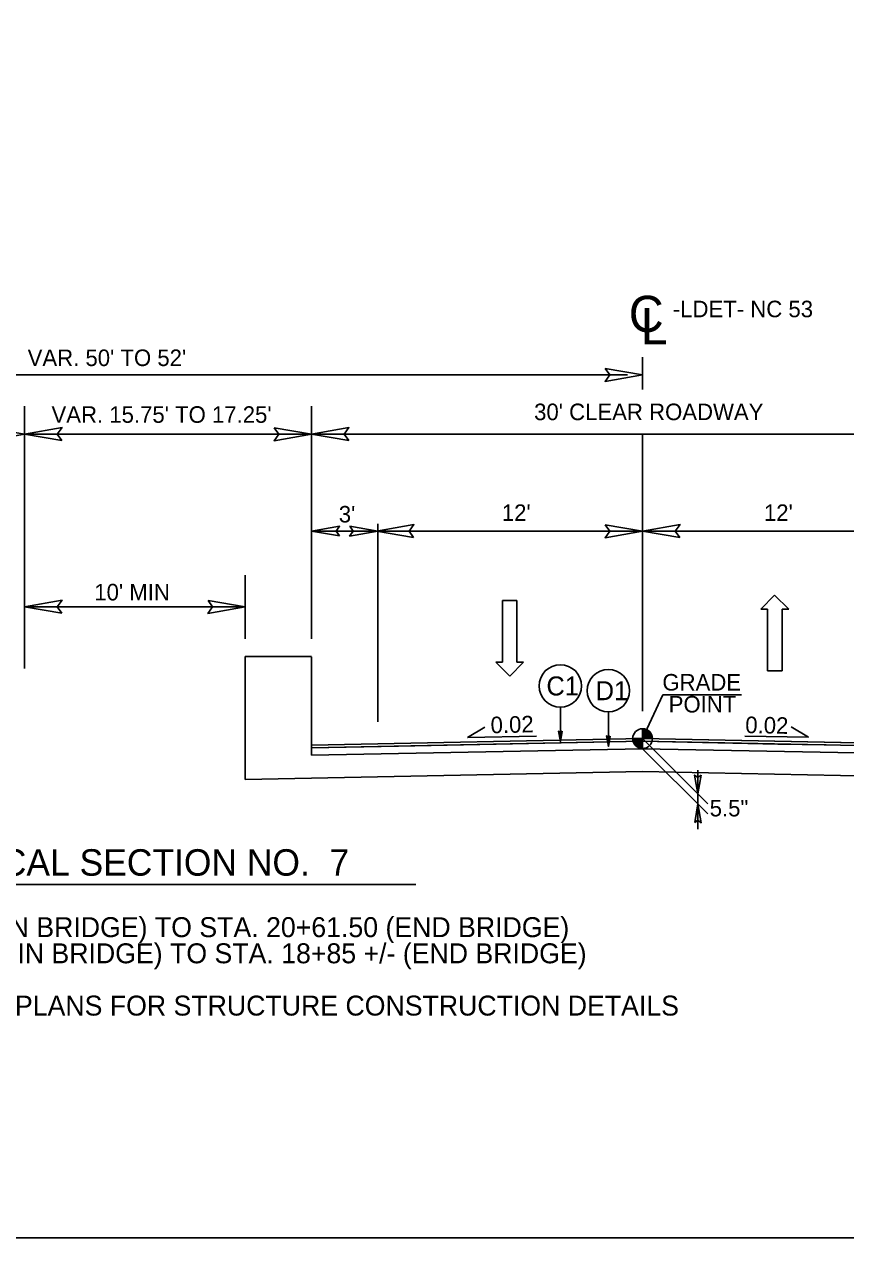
# Model space of a CAD drawing. Extents: x 1548135 to 1549339, y 868664 to 869085.
# Drawn here: x 1548209.5 to 1548246.7, y 868664.3 to 868719.3 of the extents above; entities that cross this region are included whole.
import ezdxf

# ---------------------------------------------------------------- set-up
doc = ezdxf.new("R2010")
doc.units = 0
for name, color, linetype in [('Default', 7, 'Continuous'), ('P_RDY_TC_Pvmt_Asphalt_Base_Course', 7, 'Continuous'), ('Prop Terminator CELL', 7, 'Continuous'), ('Sheet_Title_Block_Text', 7, 'Continuous'), ('Typical Curb CELL', 7, 'Continuous'), ('Typical Grade Point Symbol CELL', 7, 'Continuous'), ('Typical Hinge Slope Arterial CELL', 7, 'Continuous'), ('Typical Hinge Slope Interstate CELL', 7, 'Continuous'), ('Typical Pavement Slope Information CELL', 7, 'Continuous'), ('Typical Shoulder Slope CELL', 7, 'Continuous'), ('Typical Shoulder Slope Information CELL', 7, 'Continuous'), ('Typical Terminator CELL', 7, 'Continuous'), ('Typical Text General CELL', 7, 'Continuous'), ('Typical Text Grade Point CELL', 7, 'Continuous'), ('Typical Text ID Circle CELL', 7, 'Continuous')]:
    doc.layers.add(name, color=color, linetype=linetype)

msp = doc.modelspace()

# ---------------------------------------------------------------- linework, layer by layer
at = {"layer": 'Default'}
msp.add_lwpolyline([(1548135.05, 868774.324), (1548305.05, 868774.324), (1548305.05, 868664.324), (1548135.05, 868664.324)], close=True, dxfattribs=at)
at = {"layer": 'P_RDY_TC_Pvmt_Asphalt_Base_Course'}
for points in [[(1548235.801, 868703.729), (1548237.489, 868703.439), (1548235.792, 868703.139), (1548236.008, 868703.439)], [(1548207.801, 868701.037), (1548209.489, 868700.746), (1548207.792, 868700.446), (1548208.008, 868700.746)], [(1548211.176, 868700.455), (1548209.489, 868700.746), (1548211.186, 868701.046), (1548210.97, 868700.746)], [(1548220.801, 868701.037), (1548222.489, 868700.746), (1548220.792, 868700.446), (1548221.008, 868700.746)], [(1548224.176, 868700.455), (1548222.489, 868700.746), (1548224.186, 868701.046), (1548223.97, 868700.746)], [(1548223.755, 868696.133), (1548222.489, 868696.351), (1548223.762, 868696.576), (1548223.6, 868696.351)], [(1548224.223, 868696.569), (1548225.489, 868696.351), (1548224.216, 868696.126), (1548224.378, 868696.351)], [(1548227.117, 868696.061), (1548225.429, 868696.351), (1548227.126, 868696.651), (1548226.911, 868696.351)], [(1548235.801, 868696.642), (1548237.489, 868696.351), (1548235.792, 868696.051), (1548236.008, 868696.351)], [(1548239.176, 868696.061), (1548237.489, 868696.351), (1548239.186, 868696.651), (1548238.97, 868696.351)], [(1548211.176, 868692.63), (1548209.489, 868692.921), (1548211.186, 868693.221), (1548210.97, 868692.921)], [(1548217.801, 868693.212), (1548219.489, 868692.921), (1548217.792, 868692.621), (1548218.008, 868692.921)]]:
    msp.add_lwpolyline(points, close=True, dxfattribs=at)
at = {"layer": 'Prop Terminator CELL'}
msp.add_lwpolyline([(1548222.489, 868686.649), (1548237.489, 868686.949), (1548252.489, 868686.649), (1548252.489, 868686.524), (1548247.126, 868686.631), (1548245.814, 868686.658), (1548243.616, 868686.702), (1548237.489, 868686.824), (1548237.489, 868686.824), (1548226.425, 868686.603), (1548222.489, 868686.524)], close=True, dxfattribs=at)
at = {"layer": 'Typical Curb CELL'}
for p, q in [((1548237.489, 868686.949), (1548237.489, 868687.397)), ((1548237.041, 868686.949), (1548237.489, 868686.949)), ((1548237.488, 868686.502), (1548237.489, 868686.949)), ((1548237.489, 868686.949), (1548237.488, 868686.502)), ((1548237.936, 868686.949), (1548237.489, 868686.949))]:
    msp.add_line(p, q, dxfattribs=at)
for points in [[(1548237.493, 868687.397), (1548237.493, 868687.397), (1548237.493, 868686.949)], [(1548237.502, 868687.397), (1548237.502, 868686.949)], [(1548237.511, 868687.396), (1548237.511, 868686.949)], [(1548237.52, 868687.396), (1548237.52, 868686.949)], [(1548237.529, 868687.395), (1548237.529, 868686.949)], [(1548237.538, 868687.394), (1548237.538, 868686.949)], [(1548237.547, 868687.393), (1548237.547, 868686.949)], [(1548237.556, 868687.392), (1548237.556, 868686.949)], [(1548237.564, 868687.391), (1548237.564, 868686.949)], [(1548237.573, 868687.389), (1548237.573, 868686.949)], [(1548237.582, 868687.387), (1548237.582, 868686.949)], [(1548237.591, 868687.385), (1548237.591, 868686.949)], [(1548237.6, 868687.383), (1548237.6, 868686.949)], [(1548237.609, 868687.38), (1548237.609, 868686.949)], [(1548237.618, 868687.378), (1548237.618, 868686.949)], [(1548237.627, 868687.375), (1548237.627, 868686.949)], [(1548237.636, 868687.372), (1548237.636, 868686.949)], [(1548237.645, 868687.369), (1548237.645, 868686.949)], [(1548237.654, 868687.365), (1548237.654, 868686.949)], [(1548237.663, 868687.361), (1548237.663, 868686.949)], [(1548237.672, 868687.357), (1548237.672, 868686.949)], [(1548237.681, 868687.353), (1548237.681, 868686.949)], [(1548237.69, 868687.349), (1548237.69, 868686.949)], [(1548237.699, 868687.344), (1548237.699, 868686.949)], [(1548237.708, 868687.339), (1548237.708, 868686.949)], [(1548237.717, 868687.334), (1548237.717, 868686.949)], [(1548237.726, 868687.329), (1548237.726, 868686.949)], [(1548237.735, 868687.323), (1548237.735, 868686.949)], [(1548237.743, 868687.317), (1548237.743, 868686.949)], [(1548237.752, 868687.31), (1548237.752, 868686.949)], [(1548237.761, 868687.304), (1548237.761, 868686.949)], [(1548237.77, 868687.297), (1548237.77, 868686.949)], [(1548237.779, 868687.289), (1548237.779, 868686.949)], [(1548237.788, 868687.281), (1548237.788, 868686.949)], [(1548237.797, 868687.273), (1548237.797, 868686.949)], [(1548237.806, 868687.265), (1548237.806, 868686.949)], [(1548237.815, 868687.256), (1548237.815, 868686.949)], [(1548237.824, 868687.246), (1548237.824, 868686.949)], [(1548237.833, 868687.235), (1548237.833, 868686.949)], [(1548237.842, 868687.224), (1548237.842, 868686.949)], [(1548237.851, 868687.212), (1548237.851, 868686.949)], [(1548237.86, 868687.199), (1548237.86, 868686.949)], [(1548237.869, 868687.185), (1548237.869, 868686.949)], [(1548237.878, 868687.17), (1548237.878, 868686.949)], [(1548237.887, 868687.154), (1548237.887, 868686.949)], [(1548237.896, 868687.135), (1548237.896, 868686.949)], [(1548237.905, 868687.114), (1548237.905, 868686.949)], [(1548237.914, 868687.089), (1548237.914, 868686.949)], [(1548237.923, 868687.059), (1548237.923, 868686.949)], [(1548237.043, 868686.949), (1548237.043, 868686.9)], [(1548237.052, 868686.949), (1548237.052, 868686.848)], [(1548237.061, 868686.949), (1548237.061, 868686.816)], [(1548237.07, 868686.949), (1548237.07, 868686.789)], [(1548237.079, 868686.949), (1548237.079, 868686.768)], [(1548237.088, 868686.949), (1548237.088, 868686.749)], [(1548237.097, 868686.949), (1548237.097, 868686.732)], [(1548237.106, 868686.949), (1548237.106, 868686.716)], [(1548237.115, 868686.949), (1548237.115, 868686.703)], [(1548237.124, 868686.949), (1548237.124, 868686.69)], [(1548237.133, 868686.949), (1548237.133, 868686.678)], [(1548237.142, 868686.949), (1548237.142, 868686.667)], [(1548237.151, 868686.949), (1548237.151, 868686.656)], [(1548237.16, 868686.949), (1548237.16, 868686.646)], [(1548237.169, 868686.949), (1548237.169, 868686.636)], [(1548237.178, 868686.949), (1548237.178, 868686.627)], [(1548237.187, 868686.949), (1548237.187, 868686.619)], [(1548237.195, 868686.949), (1548237.195, 868686.611)], [(1548237.204, 868686.949), (1548237.204, 868686.603)], [(1548237.213, 868686.949), (1548237.213, 868686.596)], [(1548237.222, 868686.949), (1548237.222, 868686.589)], [(1548237.231, 868686.949), (1548237.231, 868686.583)], [(1548237.24, 868686.949), (1548237.24, 868686.577)], [(1548237.249, 868686.949), (1548237.249, 868686.571)], [(1548237.258, 868686.949), (1548237.258, 868686.565)], [(1548237.267, 868686.949), (1548237.267, 868686.56)], [(1548237.276, 868686.949), (1548237.276, 868686.555)], [(1548237.285, 868686.949), (1548237.285, 868686.55)], [(1548237.294, 868686.949), (1548237.294, 868686.546)], [(1548237.303, 868686.949), (1548237.303, 868686.542)], [(1548237.312, 868686.949), (1548237.312, 868686.538)], [(1548237.321, 868686.949), (1548237.321, 868686.534)], [(1548237.33, 868686.949), (1548237.33, 868686.53)], [(1548237.339, 868686.949), (1548237.339, 868686.527)], [(1548237.348, 868686.949), (1548237.348, 868686.525)], [(1548237.357, 868686.949), (1548237.357, 868686.521)], [(1548237.366, 868686.949), (1548237.366, 868686.52)], [(1548237.374, 868686.949), (1548237.374, 868686.517)], [(1548237.383, 868686.949), (1548237.383, 868686.515)], [(1548237.392, 868686.949), (1548237.392, 868686.513)], [(1548237.401, 868686.949), (1548237.401, 868686.511)], [(1548237.41, 868686.949), (1548237.41, 868686.509)], [(1548237.419, 868686.949), (1548237.419, 868686.508)], [(1548237.428, 868686.949), (1548237.428, 868686.506)], [(1548237.437, 868686.949), (1548237.437, 868686.505)], [(1548237.446, 868686.949), (1548237.446, 868686.504)], [(1548237.455, 868686.949), (1548237.455, 868686.503)], [(1548237.464, 868686.949), (1548237.464, 868686.503)], [(1548237.473, 868686.949), (1548237.473, 868686.502)], [(1548237.482, 868686.949), (1548237.482, 868686.502), (1548237.482, 868686.502)], [(1548237.931, 868687.013), (1548237.931, 868686.949)]]:
    msp.add_lwpolyline(points, dxfattribs=at)
msp.add_circle((1548237.488, 868686.949), 0.448, dxfattribs=at)
for start, end in [(359.9905, 89.9905), (179.9905, 269.9905)]:
    msp.add_arc((1548237.488, 868686.949), 0.448, start, end, dxfattribs=at)
at = {"layer": 'Typical Grade Point Symbol CELL'}
for p, q in [((1548237.489, 868702.765), (1548237.489, 868704.242)), ((1548236.801, 868703.439), (1548189.853, 868703.439)), ((1548209.489, 868690.126), (1548209.489, 868702.017)), ((1548222.489, 868691.462), (1548222.489, 868702.017)), ((1548209.489, 868700.746), (1548222.489, 868700.746)), ((1548237.489, 868700.746), (1548222.489, 868700.746)), ((1548237.489, 868688.197), (1548237.489, 868700.746)), ((1548237.489, 868700.746), (1548252.489, 868700.746)), ((1548225.489, 868687.703), (1548225.489, 868696.677)), ((1548237.489, 868696.351), (1548222.489, 868696.351)), ((1548224.489, 868696.351), (1548222.489, 868696.351)), ((1548237.489, 868696.351), (1548252.489, 868696.351)), ((1548219.489, 868691.462), (1548219.489, 868694.361)), ((1548209.489, 868692.921), (1548219.489, 868692.921))]:
    msp.add_line(p, q, dxfattribs=at)
at = {"layer": 'Typical Hinge Slope Arterial CELL'}
msp.add_line((1548238.413, 868688.936), (1548241.97, 868688.936), dxfattribs=at)
at = {"layer": 'Typical Hinge Slope Interstate CELL'}
for p, q in [((1548233.763, 868688.371), (1548233.763, 868686.809)), ((1548235.938, 868688.157), (1548235.938, 868686.595)), ((1548240.44, 868683.998), (1548237.489, 868686.949)), ((1548240.44, 868683.539), (1548237.489, 868686.491)), ((1548239.994, 868685.523), (1548239.996, 868682.849))]:
    msp.add_line(p, q, dxfattribs=at)
for points in [[(1548233.843, 868687.278), (1548233.763, 868686.809), (1548233.679, 868687.28), (1548233.763, 868687.221)], [(1548236.018, 868687.064), (1548235.938, 868686.595), (1548235.854, 868687.066), (1548235.938, 868687.006)], [(1548240.139, 868685.288), (1548239.994, 868684.444), (1548239.844, 868685.293), (1548239.994, 868685.185)], [(1548239.85, 868683.141), (1548239.995, 868683.985), (1548240.145, 868683.136), (1548239.995, 868683.244)]]:
    msp.add_lwpolyline(points, close=True, dxfattribs=at)
for centre in [(1548233.763, 868689.333), (1548235.938, 868689.119)]:
    msp.add_circle(centre, 0.962, dxfattribs=at)
at = {"layer": 'Typical Pavement Slope Information CELL'}
for p, q in [((1548229.563, 868686.991), (1548230.346, 868687.465)), ((1548229.563, 868686.991), (1548232.684, 868687.054)), ((1548245.01, 868687.007), (1548242.117, 868687.065)), ((1548245.01, 868687.007), (1548244.227, 868687.48))]:
    msp.add_line(p, q, dxfattribs=at)
at = {"layer": 'Typical Shoulder Slope CELL'}
msp.add_line((1548238.413, 868688.936), (1548237.489, 868686.949), dxfattribs=at)
at = {"layer": 'Typical Shoulder Slope Information CELL'}
for p, q in [((1548231.135, 868690.405), (1548231.135, 868693.205)), ((1548231.135, 868693.205), (1548231.795, 868693.205)), ((1548231.795, 868693.205), (1548231.795, 868690.405)), ((1548242.853, 868692.819), (1548243.473, 868693.449)), ((1548243.473, 868693.449), (1548244.113, 868692.819)), ((1548243.153, 868692.819), (1548242.853, 868692.819)), ((1548243.153, 868690.019), (1548243.153, 868692.819)), ((1548244.113, 868692.819), (1548243.813, 868692.819)), ((1548243.813, 868692.819), (1548243.813, 868690.019)), ((1548231.475, 868689.775), (1548230.835, 868690.405)), ((1548230.835, 868690.405), (1548231.135, 868690.405)), ((1548232.095, 868690.405), (1548231.475, 868689.775)), ((1548231.795, 868690.405), (1548232.095, 868690.405)), ((1548243.813, 868690.019), (1548243.153, 868690.019))]:
    msp.add_line(p, q, dxfattribs=at)
at = {"layer": 'Typical Terminator CELL'}
msp.add_line((1548205.498, 868680.332), (1548227.219, 868680.332), dxfattribs=at)
at = {"layer": 'Typical Text Grade Point CELL'}
for p, q in [((1548237.489, 868686.824), (1548222.489, 868686.524)), ((1548222.489, 868686.649), (1548222.489, 868686.191)), ((1548237.489, 868686.824), (1548252.489, 868686.524)), ((1548237.489, 868686.491), (1548222.489, 868686.191)), ((1548237.489, 868686.491), (1548252.489, 868686.191))]:
    msp.add_line(p, q, dxfattribs=at)
at = {"layer": 'Typical Text ID Circle CELL'}
for p, q in [((1548222.489, 868690.675), (1548219.489, 868690.675)), ((1548219.489, 868690.675), (1548219.489, 868685.089)), ((1548222.489, 868686.649), (1548222.489, 868690.649)), ((1548237.489, 868686.949), (1548222.489, 868686.649)), ((1548237.489, 868686.949), (1548252.489, 868686.649)), ((1548237.489, 868685.449), (1548219.489, 868685.089)), ((1548237.489, 868685.449), (1548255.489, 868685.089))]:
    msp.add_line(p, q, dxfattribs=at)

# ---------------------------------------------------------------- texts
at = {"layer": 'Sheet_Title_Block_Text'}
msp.add_text('C', height=1.64, dxfattribs=at).set_placement((1548236.862, 868705.378))
msp.add_text('L', height=1.641, rotation=359.9469, dxfattribs=at).set_placement((1548237.407, 868704.818))
at = {"layer": 'Typical Hinge Slope Arterial CELL'}
msp.add_text('  TYPICAL SECTION NO.  7', height=1.2, dxfattribs=at).set_placement((1548203.954, 868680.734))
at = {"layer": 'Typical Hinge Slope Interstate CELL'}
for s, height, p in [('-LDET- NC 53', 0.75, (1548238.86, 868706.045)), ("VAR. 50' TO 52'", 0.75, (1548209.627, 868703.833)), ("VAR. 15.75' TO 17.25'", 0.75, (1548210.708, 868701.261)), ("30' CLEAR ROADWAY", 0.75, (1548232.575, 868701.381)), ("10' MIN", 0.75, (1548212.647, 868693.211)), ('C1', 0.8608, (1548233.133, 868688.903)), ('D1', 0.8608, (1548235.364, 868688.689)), ('5.5"', 0.75, (1548240.53, 868683.42))]:
    msp.add_text(s, height=height, dxfattribs=at).set_placement(p)
at = {"layer": 'Typical Pavement Slope Information CELL'}
for rotation, p in [(1.4551, (1548230.612, 868687.186)), (358.8544, (1548242.137, 868687.199))]:
    msp.add_text('0.02', height=0.75, rotation=rotation, dxfattribs=at).set_placement(p)
at = {"layer": 'Typical Shoulder Slope CELL'}
for s, p in [("3' ", (1548223.725, 868696.743)), ("12'", (1548231.112, 868696.812)), ("12'", (1548242.989, 868696.812)), ('GRADE', (1548238.387, 868689.125)), ('POINT', (1548238.672, 868688.131))]:
    msp.add_text(s, height=0.75, dxfattribs=at).set_placement(p)
at = {"layer": 'Typical Text General CELL'}
for s, p in [('-L- STA. 19+06.50 (BEGIN BRIDGE) TO STA. 20+61.50 (END BRIDGE)', (1548195.275, 868677.949)), ('-LDET- STA. 15+85 +/- (BEGIN BRIDGE) TO STA. 18+85 +/- (END BRIDGE)', (1548193.444, 868676.764)), ('NOTE: SEE STRUCTURE PLANS FOR STRUCTURE CONSTRUCTION DETAILS', (1548194.479, 868674.394))]:
    msp.add_text(s, height=0.90387, dxfattribs=at).set_placement(p)

doc.saveas('drawing.dxf')
